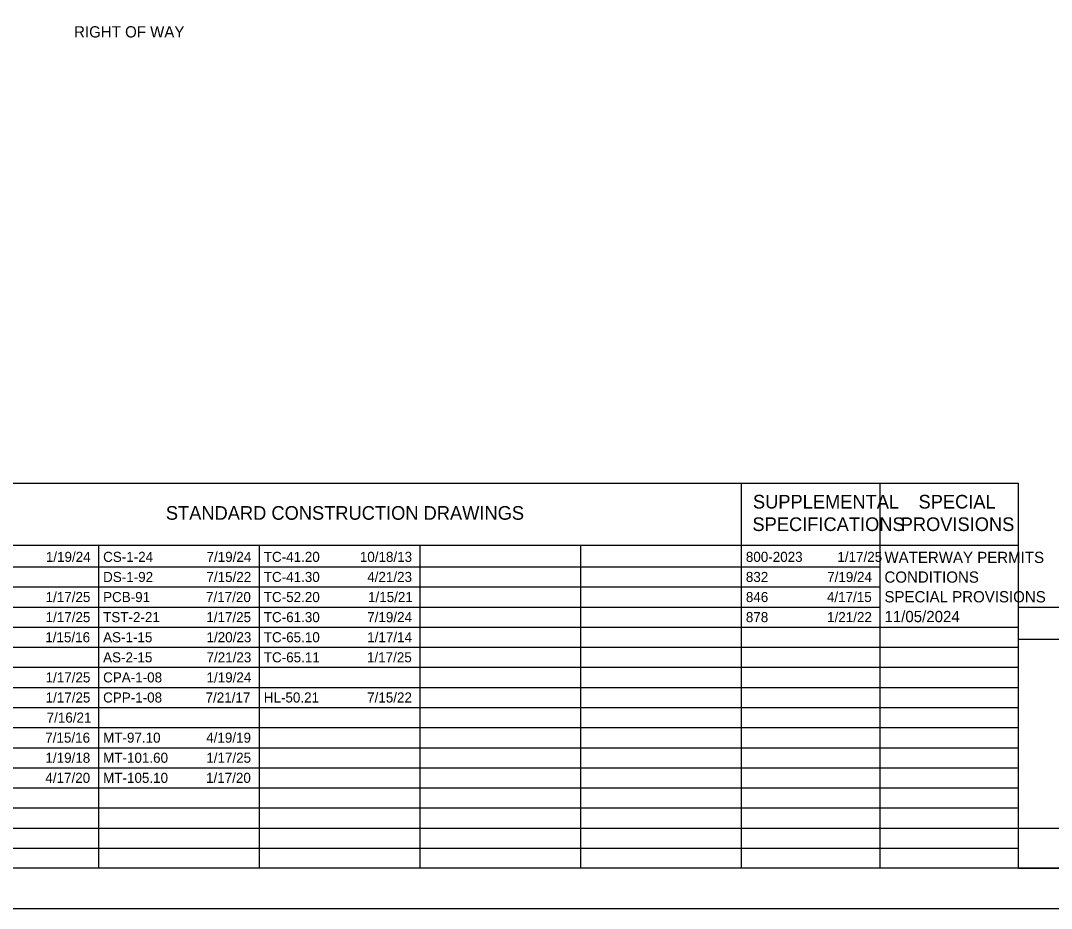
# Model space of a CAD drawing. Extents: x 0 to 48.6, y 0 to 22.
# Drawn here: x 11.18 to 24.01, y 0 to 11.05 of the extents above; entities that cross this region are included whole.
import ezdxf

# ---------------------------------------------------------------- set-up
doc = ezdxf.new("R2010")
doc.units = 0
for name, color, linetype in [('Default', 7, 'Continuous'), ('SH_Border', 7, 'Continuous'), ('SH_Cut_Line', 7, 'Continuous'), ('SH_Data', 7, 'Continuous'), ('SH_Text', 7, 'Continuous')]:
    doc.layers.add(name, color=color, linetype=linetype)

msp = doc.modelspace()

# ---------------------------------------------------------------- linework, layer by layer
at = {"layer": 'SH_Border'}
msp.add_lwpolyline([(1.5, 21.5), (33.5, 21.5), (33.5, 0.5), (1.5, 0.5)], close=True, dxfattribs=at)
at = {"layer": 'SH_Cut_Line'}
msp.add_lwpolyline([(0, 0), (34, 0), (34, 22), (0, 22)], close=True, dxfattribs=at)
at = {"layer": 'SH_Data'}
for p, q in [((10.15, 5.292), (23.6, 5.292)), ((20.15, 0.5), (20.15, 5.292)), ((21.875, 0.5), (21.875, 5.292)), ((23.6, 0.5), (23.6, 5.292)), ((10.15, 4.521), (23.6, 4.521)), ((12.15, 0.5), (12.15, 4.521)), ((14.15, 0.5), (14.15, 4.521)), ((16.15, 0.5), (16.15, 4.521)), ((18.15, 0.5), (18.15, 4.521)), ((10.15, 4.25), (21.875, 4.25)), ((10.15, 4), (21.875, 4)), ((10.15, 3.75), (21.875, 3.75)), ((23.6, 0.5), (23.6, 3.75)), ((23.6, 3.75), (26.4, 3.75)), ((10.15, 3.5), (23.6, 3.5)), ((23.6, 3.35), (26.4, 3.35)), ((10.15, 3.25), (23.6, 3.25)), ((10.15, 3), (23.6, 3)), ((10.15, 2.75), (23.6, 2.75)), ((10.15, 2.5), (23.6, 2.5)), ((10.15, 2.25), (23.6, 2.25)), ((10.15, 2), (23.6, 2)), ((10.15, 1.75), (23.6, 1.75)), ((10.15, 1.5), (23.6, 1.5)), ((10.15, 1.25), (23.6, 1.25)), ((10.15, 1), (23.6, 1)), ((10.15, 0.75), (23.6, 0.75)), ((23.6, 0.5), (26.4, 0.5))]:
    msp.add_line(p, q, dxfattribs=at)
msp.add_lwpolyline([(23.6, 0.5), (23.6, 1), (26.4, 1), (26.4, 0.5)], close=True, dxfattribs=at)

# ---------------------------------------------------------------- texts
at = {"layer": 'Default'}
for s, height, p in [('1/19/24', 0.125, (11.492, 4.312)), ('CS-1-24', 0.125, (12.205, 4.312)), ('7/19/24', 0.125, (13.492, 4.312)), ('TC-41.20', 0.125, (14.205, 4.312)), ('10/18/13', 0.125, (15.4, 4.312)), ('800-2023', 0.125, (20.205, 4.312)), ('1/17/25', 0.125, (21.344, 4.312)), ('WATERWAY PERMITS', 0.14, (21.93, 4.298)), ('DS-1-92', 0.125, (12.205, 4.062)), ('7/15/22', 0.125, (13.491, 4.062)), ('TC-41.30', 0.125, (14.205, 4.062)), ('4/21/23', 0.125, (15.492, 4.062)), ('832', 0.125, (20.205, 4.062)), ('7/19/24', 0.125, (21.217, 4.062)), ('CONDITIONS', 0.14, (21.93, 4.053)), ('1/17/25', 0.125, (11.489, 3.812)), ('PCB-91', 0.125, (12.205, 3.812)), ('7/17/20', 0.125, (13.486, 3.812)), ('TC-52.20', 0.125, (14.205, 3.812)), ('1/15/21', 0.125, (15.502, 3.812)), ('846', 0.125, (20.205, 3.812)), ('4/17/15', 0.125, (21.214, 3.812)), ('SPECIAL PROVISIONS', 0.14, (21.93, 3.808)), ('1/17/25', 0.125, (11.489, 3.562)), ('TST-2-21', 0.125, (12.205, 3.562)), ('1/17/25', 0.125, (13.489, 3.562)), ('TC-61.30', 0.125, (14.205, 3.562)), ('7/19/24', 0.125, (15.492, 3.562)), ('878', 0.125, (20.205, 3.562)), ('1/21/22', 0.125, (21.216, 3.562)), ('11/05/2024', 0.14, (21.93, 3.562)), ('1/15/16', 0.125, (11.485, 3.312)), ('AS-1-15', 0.125, (12.205, 3.312)), ('1/20/23', 0.125, (13.492, 3.312)), ('TC-65.10', 0.125, (14.205, 3.312)), ('1/17/14', 0.125, (15.492, 3.312)), ('AS-2-15', 0.125, (12.205, 3.062)), ('7/21/23', 0.125, (13.492, 3.062)), ('TC-65.11', 0.125, (14.205, 3.062)), ('1/17/25', 0.125, (15.489, 3.062)), ('1/17/25', 0.125, (11.489, 2.812)), ('CPA-1-08', 0.125, (12.205, 2.812)), ('1/19/24', 0.125, (13.492, 2.812)), ('1/17/25', 0.125, (11.489, 2.562)), ('CPP-1-08', 0.125, (12.205, 2.562)), ('7/21/17', 0.125, (13.48, 2.562)), ('HL-50.21', 0.125, (14.205, 2.562)), ('7/15/22', 0.125, (15.491, 2.562)), ('7/16/21', 0.125, (11.502, 2.312)), ('7/15/16', 0.125, (11.485, 2.062)), ('MT-97.10', 0.125, (12.205, 2.062)), ('4/19/19', 0.125, (13.488, 2.062)), ('1/19/18', 0.125, (11.487, 1.812)), ('MT-101.60', 0.125, (12.205, 1.812)), ('1/17/25', 0.125, (13.489, 1.812)), ('4/17/20', 0.125, (11.486, 1.562)), ('MT-105.10', 0.125, (12.205, 1.562)), ('1/17/20', 0.125, (13.486, 1.562))]:
    msp.add_text(s, height=height, dxfattribs=at).set_placement(p)
at = {"layer": 'SH_Text'}
for s, height, p in [('RIGHT OF WAY                        ', 0.14, (11.844, 10.838)), ('SUPPLEMENTAL', 0.17, (20.293, 4.976)), ('SPECIAL', 0.17, (22.354, 4.976)), ('STANDARD CONSTRUCTION DRAWINGS', 0.17, (12.986, 4.836)), ('SPECIFICATIONS', 0.17, (20.287, 4.696)), ('PROVISIONS', 0.17, (22.132, 4.696))]:
    msp.add_text(s, height=height, dxfattribs=at).set_placement(p)

doc.saveas('drawing.dxf')
